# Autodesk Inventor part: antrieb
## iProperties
Shininess: 64.0
Length Units: 11269
Angle Units: 11279
Time Units: 11290
Mass Units: 11283
Length Display Precision: 3
Angle Display Precision: 2
Compacted: True
Part Number: antrieb
Document SubType Name: Modeling
Created: 2003-02
Material: Standard
Designer: Katja / W. Holzwarth
Density: 0.0
Volumn: 0.0
Area: 0.0
PropertySet Name: Model Information
Control State: 0
Master: False
Checked Out: False
Author: Katja / W. Holzwarth
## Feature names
1. Extrusion1
2. Extrusion3
3. Extrusion4
4. Extrusion5
